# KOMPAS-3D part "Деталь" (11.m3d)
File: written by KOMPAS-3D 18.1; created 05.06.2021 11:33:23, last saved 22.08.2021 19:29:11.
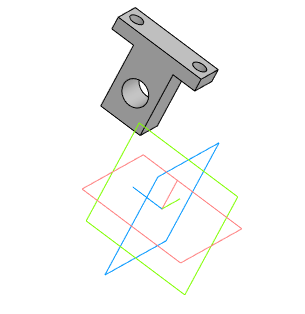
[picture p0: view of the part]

Document properties: Автор: 111; Полное имя файла: C:\Users\admin\Desktop\ffb\11.m3d

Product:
- Part/product: Деталь
    Масса: 0.0808172

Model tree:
1. Эскиз:2
2. Элемент выдавливания:1
     Расстояние 1 = 14
3. Эскиз:3  (with: Элемент выдавливания:1)
4. Элемент выдавливания:2
     Расстояние 2 = 6.15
